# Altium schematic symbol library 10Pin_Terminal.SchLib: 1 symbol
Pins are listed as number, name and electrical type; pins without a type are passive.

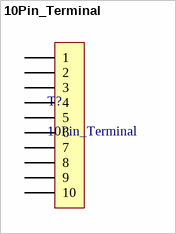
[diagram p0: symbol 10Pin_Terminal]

## 10Pin_Terminal
designator T?
footprint 10Pin_Terminal
pins: 1, 2, 3, 4, 5, 6, 7, 8, 9, 10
